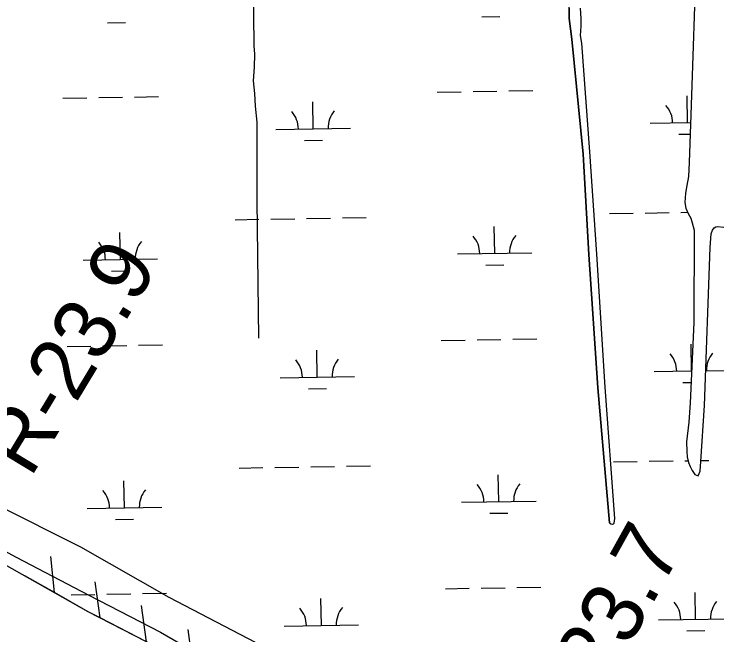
# Model space of a CAD drawing. Extents: x 3855477 to 3893699, y 299188 to 325115.
# Drawn here: x 3862374 to 3863316, y 316895 to 317727 of the extents above; entities that cross this region are included whole.
import ezdxf

# ---------------------------------------------------------------- set-up
doc = ezdxf.new("R2010")
doc.units = 0
for name, color, linetype in [('V-LEVE-TOET', 7, 'Continuous'), ('V-RIVR-EDGE', 7, 'Continuous'), ('V-RIVR-RANG-IDEN', 7, 'Continuous'), ('V-RRAP-FSHR', 7, 'Continuous'), ('V-TOPO-SHOR', 7, 'Continuous'), ('V-WETL-SWMP', 7, 'Continuous')]:
    doc.layers.add(name, color=color, linetype=linetype)

msp = doc.modelspace()

# ---------------------------------------------------------------- linework, layer by layer
at = {"layer": 'V-LEVE-TOET'}
for points in [[(3864365.02, 315977.84), (3864291.52, 316022.98), (3864202.21, 316071.98), (3864114.46, 316118.32), (3864011.47, 316172.75), (3863900.03, 316227.26), (3863792.82, 316282.79), (3863620.45, 316372.27), (3863488.09, 316447.6), (3863361.48, 316517.59), (3863231.7, 316587.09), (3863120.34, 316649.52), (3863032.12, 316702.21), (3862931.78, 316757.14), (3862812.04, 316826.53), (3862709.02, 316878.84), (3862581.85, 316945.14), (3862463.67, 317012.4), (3862350.14, 317069.05)], [(3862265.5, 317059.36), (3862376.89, 316999.04), (3862474.1, 316948.37), (3862570.28, 316898.77), (3862675.32, 316837.98)]]:
    msp.add_lwpolyline(points, dxfattribs=at)
at = {"layer": 'V-RIVR-EDGE'}
msp.add_spline([(3861643.53, 317089.49), (3861674.18, 317073.47), (3861698.46, 317060.26), (3861723.94, 317049.04), (3861744.63, 317038.63), (3861771.7, 317026.2), (3861804.75, 317012.17), (3861824.65, 317002.96), (3861840.97, 316994.15), (3861856.1, 316990.13), (3861866.47, 316990.1), (3861879.61, 316985.69), (3861900.3, 316974.08), (3861917.82, 316966.46), (3862001.43, 316931.98), (3862028.89, 316919.56), (3862036.87, 316919.94), (3862045.23, 316916.33), (3862058.76, 316907.93), (3862071.5, 316904.31), (3862089.42, 316899.08), (3862105.35, 316894.26), (3862127.64, 316884.64), (3862144.36, 316874.64), (3862154.31, 316868.24), (3862166.65, 316864.62), (3862190.95, 316859.78), (3862210.07, 316856.54), (3862236.75, 316848.9), (3862259.45, 316840.88), (3862302.44, 316817.65), (3862327.52, 316808.43), (3862335.49, 316808.41), (3862355.41, 316803.18), (3862386.07, 316793.93), (3862408.77, 316787.5), (3862429.48, 316781.07), (3862460.14, 316771.43), (3862476.86, 316765.01), (3862487.22, 316762.2), (3862505.52, 316751), (3862525.42, 316737.4), (3862548.5, 316722.99), (3862579.14, 316706.58)], degree=3, dxfattribs=at)
at = {"layer": 'V-RRAP-FSHR'}
for p, q in [((3862428.19, 316951.67), (3862423.44, 317000.28)), ((3862489.48, 316917.89), (3862482.89, 316966.27)), ((3862551.71, 316885.84), (3862545.12, 316934.23)), ((3862613.95, 316853.8), (3862607.36, 316902.18))]:
    msp.add_line(p, q, dxfattribs=at)
for points in [[(3863755.9, 316222.32), (3863272.86, 316481.96), (3862847.86, 316733.36), (3862473.5, 316926.11), (3861935.6, 317229.54), (3861789.61, 317312.68)], [(3862428.19, 316951.67), (3862388.58, 316974.01)], [(3862489.48, 316917.89), (3862473.5, 316926.11), (3862428.18, 316951.67)], [(3862551.71, 316885.84), (3862489.48, 316917.89)]]:
    msp.add_lwpolyline(points, dxfattribs=at)
at = {"layer": 'V-TOPO-SHOR'}
for points in [[(3863172.46, 317045.14), (3863156.54, 317226.04), (3863144.88, 317404.5), (3863136.9, 317538.94), (3863121.82, 317692.98), (3863119.9, 317707.13), (3863118.45, 317720.81), (3863118.44, 317734.78), (3863115.22, 317761.81), (3863113.54, 317798.52), (3863113.77, 317866.96), (3863113.54, 317891.58), (3863112.48, 317911.44), (3863111.31, 317921.62), (3863109.17, 317928.94), (3863104.77, 317948.84), (3863099.41, 318030.21)], [(3862702.24, 317292.69), (3862699.83, 317476.8), (3862699.91, 317581.76), (3862697.69, 317603.33), (3862697.01, 317620.28), (3862695.31, 317637.09), (3862696.51, 317655.6), (3862696.69, 317672.83), (3862695.8, 317684.19), (3862695.22, 317767.04), (3862689.12, 317871.78)], [(3863289.13, 317816.12), (3863281.41, 317591.65), (3863279.17, 317527.83), (3863278.5, 317509.26), (3863275.99, 317497.22), (3863274.14, 317486.76), (3863273.21, 317474.06), (3863274.72, 317466.58), (3863277.98, 317459.56), (3863281.25, 317453.33), (3863283.41, 317446.96), (3863286.01, 317437.24), (3863285.53, 317313.7), (3863280.45, 317205.92), (3863278.91, 317180.21), (3863275.78, 317153.88), (3863276.28, 317140.85), (3863276.68, 317133.54), (3863278.35, 317126.07), (3863280.52, 317120.48), (3863283.32, 317115.22), (3863286.92, 317110.1), (3863288.97, 317108.96), (3863291.35, 317108.3), (3863294.11, 317114.15), (3863294.72, 317127.48)], [(3863172.46, 317045.14), (3863174.19, 317044.01), (3863174.51, 317043.85), (3863176.41, 317043.2), (3863176.88, 317043.19), (3863177.84, 317043.82), (3863178.65, 317044.92), (3863179.5, 317051.11), (3863166.56, 317227.04), (3863155.21, 317405.19), (3863145.99, 317542.18), (3863135.1, 317687.92), (3863133.46, 317697.94), (3863134.23, 317710.64), (3863134.17, 317720.64), (3863133.36, 317734.63)], [(3863294.72, 317127.48), (3863299.94, 317202.23), (3863307.21, 317414), (3863308.51, 317432.25), (3863310.47, 317437.15), (3863312.72, 317440.3), (3863314.8, 317441.71), (3863317.19, 317442.16), (3863325.75, 317441.44)]]:
    msp.add_lwpolyline(points, dxfattribs=at)
at = {"layer": 'V-WETL-SWMP'}
for p, q in [((3863001.26, 317723.17), (3863025.26, 317723.56)), ((3862499.42, 317715), (3862523.42, 317715.39)), ((3862941.49, 317622.18), (3862973.49, 317622.71)), ((3862989.49, 317622.97), (3863021.48, 317623.49)), ((3863037.48, 317623.75), (3863069.48, 317624.27)), ((3862439.65, 317614.01), (3862471.65, 317614.53)), ((3862487.65, 317614.79), (3862519.64, 317615.31)), ((3862535.64, 317615.57), (3862567.64, 317616.09)), ((3863277.05, 317581.21), (3863276.46, 317617.21)), ((3862775.21, 317573.04), (3862774.62, 317609.03)), ((3863227.06, 317580.4), (3863281.05, 317581.28)), ((3862725.22, 317572.22), (3862825.2, 317573.85)), ((3863265.3, 317565.59), (3863280.5, 317565.84)), ((3862763.46, 317557.41), (3862787.46, 317557.81)), ((3863268.16, 317460.98), (3863277.25, 317461.13)), ((3862670.33, 317451.24), (3862702.33, 317451.76)), ((3862718.33, 317452.02), (3862750.32, 317452.55)), ((3862766.32, 317452.81), (3862798.32, 317453.33)), ((3862814.32, 317453.59), (3862846.31, 317454.11)), ((3863172.18, 317459.42), (3863204.17, 317459.94)), ((3863220.17, 317460.2), (3863252.17, 317460.72)), ((3863018.43, 317406.17), (3863017.84, 317442.16)), ((3862516.59, 317397.99), (3862516, 317433.98)), ((3862968.44, 317405.35), (3863068.42, 317406.98)), ((3862466.6, 317397.18), (3862566.58, 317398.8)), ((3863006.68, 317390.54), (3863030.68, 317390.93)), ((3862504.84, 317382.37), (3862528.84, 317382.76)), ((3863042.9, 317291.12), (3863074.9, 317291.64)), ((3862493.07, 317282.16), (3862525.06, 317282.68)), ((3862541.06, 317282.94), (3862573.05, 317283.46)), ((3862946.91, 317289.55), (3862978.91, 317290.07)), ((3862994.91, 317290.33), (3863026.9, 317290.86)), ((3863282.47, 317248.75), (3863281.88, 317284.58)), ((3862445.07, 317281.38), (3862477.07, 317281.9)), ((3862780.63, 317240.41), (3862780.04, 317276.4)), ((3863232.48, 317247.77), (3863282.46, 317248.58)), ((3863301.54, 317248.89), (3863332.46, 317249.4)), ((3862730.63, 317239.59), (3862830.62, 317241.22)), ((3863270.72, 317232.96), (3863281.73, 317233.14)), ((3862768.88, 317224.78), (3862792.88, 317225.17)), ((3863177.6, 317126.79), (3863209.59, 317127.31)), ((3863225.59, 317127.57), (3863257.58, 317128.09)), ((3863273.58, 317128.35), (3863277.83, 317128.42)), ((3863294.81, 317128.7), (3863305.58, 317128.87)), ((3862675.75, 317118.61), (3862707.75, 317119.13)), ((3862723.75, 317119.39), (3862755.74, 317119.92)), ((3862771.74, 317120.18), (3862803.74, 317120.7)), ((3862819.73, 317120.96), (3862851.73, 317121.48)), ((3863023.85, 317073.53), (3863023.26, 317109.53)), ((3862522.01, 317065.36), (3862521.42, 317101.35)), ((3862472.02, 317064.54), (3862572, 317066.17)), ((3862973.86, 317072.72), (3863073.84, 317074.35)), ((3863012.1, 317057.91), (3863036.1, 317058.3)), ((3862510.26, 317049.73), (3862534.26, 317050.13)), ((3862952.33, 316956.92), (3862984.33, 316957.44)), ((3863000.33, 316957.7), (3863032.32, 316958.23)), ((3863048.32, 316958.49), (3863080.32, 316959.01)), ((3862450.49, 316948.75), (3862482.49, 316949.27)), ((3862498.48, 316949.53), (3862530.48, 316950.05)), ((3862546.48, 316950.31), (3862578.47, 316950.83)), ((3862786.05, 316907.78), (3862785.46, 316943.77)), ((3863287.89, 316915.95), (3863287.3, 316951.95)), ((3863237.89, 316915.14), (3863337.88, 316916.77)), ((3862736.05, 316906.96), (3862836.04, 316908.59)), ((3863276.14, 316900.33), (3863300.14, 316900.72))]:
    msp.add_line(p, q, dxfattribs=at)
for points in [[(3863289.13, 317816.12), (3863281.41, 317591.65), (3863279.17, 317527.83), (3863278.5, 317509.26), (3863275.99, 317497.22), (3863274.14, 317486.76), (3863273.21, 317474.06), (3863274.72, 317466.58), (3863277.98, 317459.56), (3863281.25, 317453.33), (3863283.41, 317446.96), (3863286.01, 317437.24), (3863285.53, 317313.7), (3863280.45, 317205.92), (3863278.91, 317180.21), (3863275.78, 317153.88), (3863276.28, 317140.85), (3863276.68, 317133.54), (3863278.35, 317126.06), (3863280.52, 317120.48), (3863283.32, 317115.21), (3863286.92, 317110.1), (3863288.97, 317108.96), (3863291.35, 317108.3), (3863294.11, 317114.15), (3863294.72, 317127.48), (3863299.94, 317202.23), (3863307.21, 317414), (3863308.51, 317432.25), (3863310.47, 317437.15), (3863312.72, 317440.3), (3863314.8, 317441.71), (3863317.19, 317442.16)], [(3863118.44, 317734.78), (3863118.45, 317720.81), (3863119.9, 317707.13), (3863121.82, 317692.98), (3863136.9, 317538.94), (3863144.88, 317404.5), (3863156.54, 317226.04), (3863172.46, 317045.14), (3863174.19, 317044.01), (3863174.51, 317043.85), (3863176.41, 317043.2), (3863176.88, 317043.19), (3863177.84, 317043.82), (3863178.65, 317044.92), (3863179.51, 317051.11), (3863166.56, 317227.04), (3863155.21, 317405.19), (3863145.99, 317542.18), (3863135.1, 317687.92), (3863133.46, 317697.94), (3863134.23, 317710.64), (3863134.17, 317720.64), (3863133.36, 317734.63)]]:
    msp.add_lwpolyline(points, dxfattribs=at)
for centre, start, end in [((3863221.81, 317580.79), 0.16154, 41.7052), ((3862719.97, 317572.61), 0.16154, 41.7052), ((3862830.44, 317574.41), 140.16154, 181.7052), ((3862963.19, 317405.74), 0.16154, 41.7052), ((3863073.66, 317407.54), 140.16154, 181.7052), ((3862461.35, 317397.56), 0.16154, 41.7052), ((3862571.82, 317399.36), 140.16154, 181.7052), ((3863337.7, 317249.96), 140.16154, 181.7052), ((3862725.38, 317239.98), 0.16154, 41.7052), ((3862835.86, 317241.78), 140.16154, 181.7052), ((3863227.23, 317248.16), 0.16154, 41.7052), ((3862968.61, 317073.11), 0.16154, 41.7052), ((3863079.08, 317074.91), 140.16154, 181.7052), ((3862466.77, 317064.93), 0.16154, 41.7052), ((3862577.24, 317066.73), 140.16154, 181.7052), ((3863232.64, 316915.53), 0.16154, 41.7052), ((3863343.12, 316917.33), 140.16154, 181.7052), ((3862730.8, 316907.35), 0.16154, 41.7052), ((3862841.27, 316909.15), 140.16154, 181.7052)]:
    msp.add_arc(centre, 35.25, start, end, dxfattribs=at)

# ---------------------------------------------------------------- texts
at = {"layer": 'V-RIVR-RANG-IDEN'}
for s, rotation, p in [('R-23.9', 58.86317, (3862396.14, 317104.07)), ('R-23.7', 60.94865, (3863110.79, 316721.12))]:
    msp.add_text(s, height=83, rotation=rotation, dxfattribs=at).set_placement(p)

doc.saveas('drawing.dxf')
